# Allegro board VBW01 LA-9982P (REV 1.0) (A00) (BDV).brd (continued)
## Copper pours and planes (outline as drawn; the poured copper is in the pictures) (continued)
N19792312 on BOTTOM (solid shape): 24.27,27.21 24.27,26.33 24.13,26.18 22.56,26.18 22.51,26.23 22.51,26.88 22.95,27.32 24.17,27.32
N21178712 on TOP (solid shape): 132.14,174.01 132.14,172.45 132.04,172.36 129.89,172.36 129.27,172.97 129.27,174.2 129.35,174.28 131.87,174.28
N32320781 on BOTTOM (solid shape): 140.81,165.34 140.81,164.41 141.7,163.52 141.7,162.63 141.63,162.57 140.11,162.57 139.86,162.32 139.86,162 140.11,161.75 141.57,161.75 141.7,161.62 141.7,161.17 141.44,160.92 138.71,160.92 138.27,161.36 138.27,164.92 138.71,165.36 140.78,165.36
N46608740 on BOTTOM (solid shape): 142.33,167.02 143.09,167.02 143.22,166.89 143.22,165.43 143.16,165.36 142.27,165.36 142.08,165.56 138.59,165.56 138.27,165.87 138.27,167.27 138.46,167.46 141.89,167.46
N46660696 on TOP (solid shape): 109.12,144.03 109.12,142.57 108.87,142.31 107.98,142.31 107.85,142.44 107.85,143.2 107.66,143.39 107.03,143.39 106.9,143.52 106.9,144.03 107.03,144.16 108.99,144.16
N47008006 on TOP (solid shape): 129.18,177.77 129.18,176.3 129.08,176.2 129.08,174.62 128.98,174.51 128.1,174.51 128,174.62 128,177.75 128.16,177.91 129.04,177.91
N47008041 on TOP (solid shape): 129.07,174.15 129.07,172.9 129.88,172.09 129.88,170.78 129.81,170.71 129.27,170.71 129.22,170.77 129.22,172.13 128.67,172.68 128.67,174.17 128.76,174.26 128.97,174.26
N47008301 on TOP (solid shape): 129.44,179.52 129.44,178.45 129.27,178.28 127.98,178.28 127.75,178.51 127.75,179.68 127.92,179.85 129.12,179.85
N47305899 on TOP (solid shape): 211.74,63.45 211.74,61.86 211.67,61.8 210.15,61.8 209.58,62.37 209.58,63.32 209.77,63.51 211.67,63.51
N47415258 on TOP (solid shape): 135.79,21.63 134.7,20.54 132.56,20.54 132.3,20.8 132.3,21.76 132.43,21.88 133.63,21.88 134.14,22.39 134.14,22.71 135.79,22.71
N47415272 on TOP (solid shape): 120.87,22.84 120.87,22.2 120.92,22.16 121.9,22.16 122.01,22.05 122.01,20.93 121.89,20.8 119.73,20.8 119.15,21.38 119.15,22.9 120.81,22.9
N47417471 on BOTTOM (solid shape): 109.99,24.55 109.99,23.79 110.12,23.66 110.12,21.07 109.76,20.71 109.12,20.71 108.99,20.84 108.99,21.28 107.6,21.28 107.6,20.78 107.53,20.71 107.03,20.71 106.45,21.28 106.45,23.44 106.99,23.98 108.79,23.98 109.1,23.66 109.61,23.66 109.74,23.79 109.74,24.55 109.8,24.62 109.93,24.62
N47420895 on BOTTOM (solid shape): 161.83,11.5 161.83,9.92 161.76,9.85 160.62,9.85 159.73,10.74 157.06,10.74 156.94,10.87 156.94,11.38 157.06,11.5 160.62,11.5 160.68,11.57 161.76,11.57
N64564173 on TOP (solid shape): 183.61,170.57 183.61,170 184.05,169.56 184.05,168.73 183.99,168.67 183.35,168.67 183.23,168.79 183.23,169.37 182.72,169.87 182.72,170.57 182.78,170.64 183.54,170.64
N64564191 on TOP (solid shape): 180.75,171.33 180.75,170.7 181,170.44 181.7,170.44 181.83,170.32 181.83,169.62 181.7,169.49 179.8,169.49 179.67,169.62 179.67,171.27 179.8,171.4 180.69,171.4

Small or netless copper shapes (teardrops, artwork), in the pictures only: 20 on TOP, 360 on BOTTOM, 1 on IN1

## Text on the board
Ref Des/Silkscreen Bottom: H10 | DDR3L-SODIMM | H6
User.Comments: LA9982P | Monika_Song | 2013-02-19 | 2014-02-19 | VBW01 | 0.3(X02)
BODY_CENTER: 183.05 | 174.00 | 104.45 | 88.30 | 55.01 | 16.00 | 1.25 | 103.70 | 58.34 | 24.93 | 4.55 | 168.55 | 173.50
USER_PART_NUM_BOTTOM: 2.80 | n | 9.00 | 6.00 | 3.70 | 8.00 | 3.30 | 2.30 | 3.20 | 5.80
DEVICE_TYPE_BOTTOM: 203.30 | 198.28 | 194.00 | 144.40 | 116.00 | 97.60 | 84.00 | 71.90 | 61.00 | 29.40 | 21.10 | 2.60 | 0.00 | 149.90 | 114.20 | 104.50 | 98.76 | 67.00 | 33.20 | 8.50 | 76.50 | 89.50 | 89.55 | 115.85 | 124.16 | 139.60 | 163.50 | 182.60
PAGE_OUTLINE: WHITE PAINT
User.7: 217.12 | 214.88 | 212.51 | 209.10 | 213.45 | 179.85 | 155.58 | 158.85 | 131.90 | 69.68 | 14.60 | 0.00 | 1.85 | 3.45 | SCALE | 1.000 | 12.70 | 27.00 | 44.60 | 62.20 | 17.00 | 81.47 | 90.60 | 103.25 | 105.45 | 145.77 | 32.50 | 40.80 | 93.32 | 154.95 | 183.80
User.8: WHITE PAINT
User.9: 0.00
User.10: 217.12 | 214.88 | 212.51 | 209.10 | 213.45 | 179.85 | 155.58 | 158.85 | 131.90 | 69.68 | 14.60 | 0.00 | 1.85 | 3.45 | SCALE | 1.000 | 12.70 | 27.00 | 44.60 | 62.20 | 17.00 | 81.47 | 90.60 | 103.25 | 105.45 | 145.77 | 32.50 | 40.80 | 93.32 | 154.95 | 183.80
User.11: 183.05 | 174.00 | 104.45 | 88.30 | 55.01 | 16.00 | 1.25 | 103.70 | 58.34 | 24.93 | 4.55 | 168.55 | 173.50
User.14: 2.80 | n | 9.00 | 6.00 | 3.70 | 8.00 | 3.30 | 2.30 | 3.20 | 5.80
User.15: 203.30 | 198.28 | 194.00 | 144.40 | 116.00 | 97.60 | 84.00 | 71.90 | 61.00 | 29.40 | 21.10 | 2.60 | 0.00 | 149.90 | 114.20 | 104.50 | 98.76 | 67.00 | 33.20 | 8.50 | 76.50 | 89.50 | 89.55 | 115.85 | 124.16 | 139.60 | 163.50 | 182.60
User.16: WHITE PAINT
User.17: WHITE PAINT
User.18: 0.00
User.38: Width/space | 4.5/5.5 | 5 / 8 | 4 / 6.5 | 4 / 12 | SB_1_2mm-6L and 8L and 10L(4mil & 5mil 50ohm)_120807 | 100 ohm
User.39: FIGURE | SIZE | 8.0 | 10.0 | 22.0 | 24.0 | 28.0 | 31.0 | 35.0 | 36.0 | 39.0 | 91.0 | 110.0 | 130.0 | 146.0 | 40.0 | 43.0 | 47.0 | 63.0 | 71.0 | 28.0x16.0 | 59.0x24.0 | 63.0x28.0 | 71.0x20.0 | 71.0x31.0 | 79.0x31.0 | 87.0x43.0 | 91.0x35.0 | 94.0x39.0 | 110.0x39.0 | 146.0x126.0 | DRILL CHART: TOP to BOTTOM | ALL UNITS ARE IN MILS | PLATED | NON-PLATED | QTY | 4757 | 708 | 19 | 6 | 25 | 22 | 8 | 4 | 9 | 2 | 1 | 7 | 26
